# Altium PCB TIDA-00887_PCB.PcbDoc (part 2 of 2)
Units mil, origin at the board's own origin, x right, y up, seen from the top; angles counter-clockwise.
Board outline 2665 x 2727 mil, 4 copper layers (Top Layer, GND, 3p3V, Bottom Layer), stack 61.2 mil thick; 96 components, 53 nets, 301 pads, 167 vias.
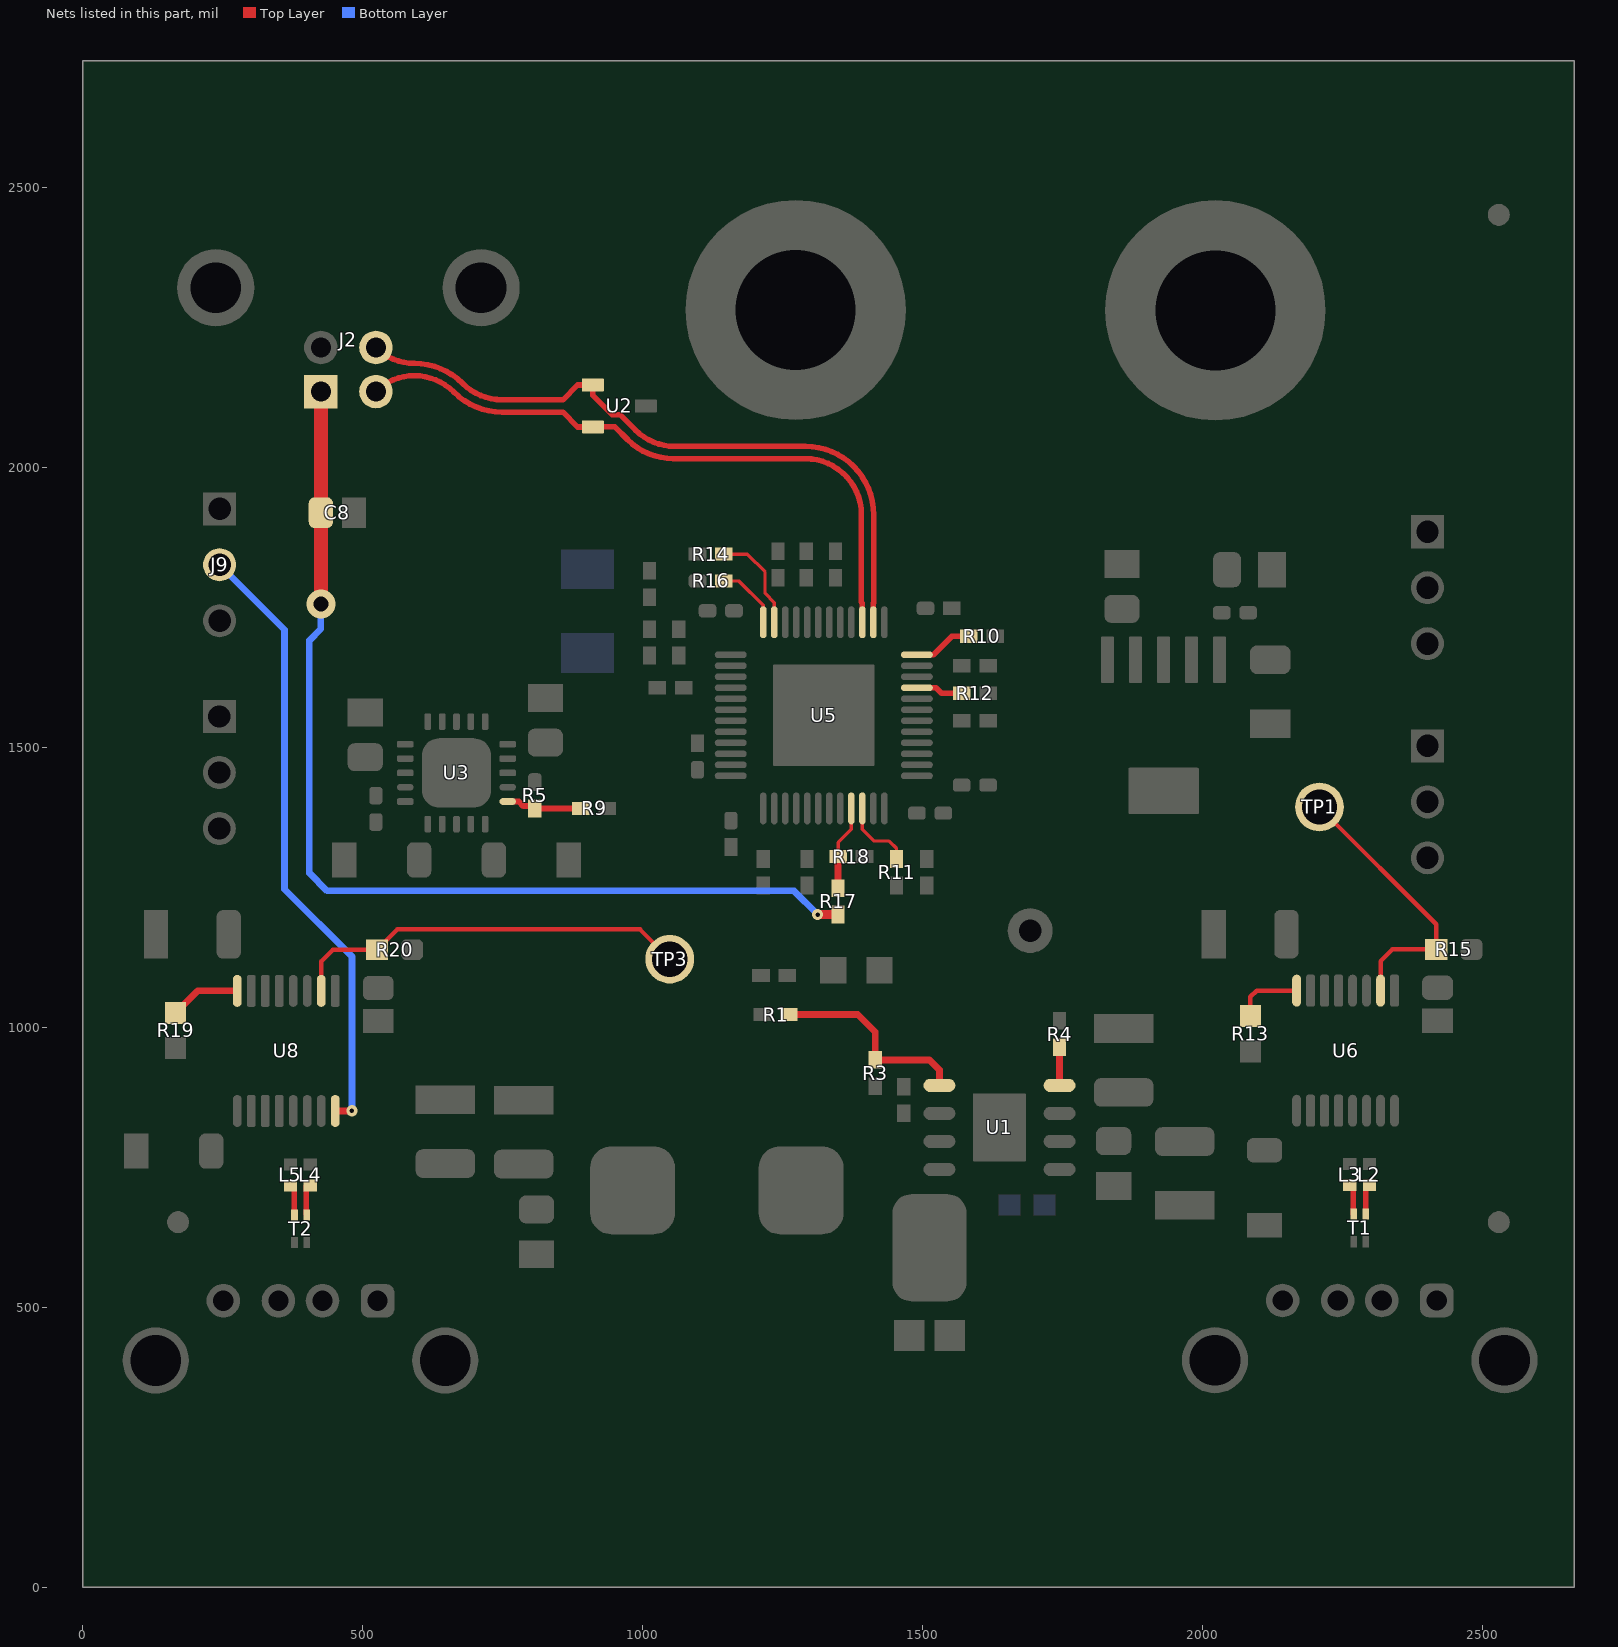
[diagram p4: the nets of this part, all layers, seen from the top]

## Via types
v1: diameter 19.68, hole 7.87, Top Layer to Bottom Layer, tented both sides, 115 vias
v2: diameter 19.68, hole 7.87, Top Layer to Bottom Layer, 30 vias
v3: diameter 34, hole 16, Top Layer to Bottom Layer, tented both sides, 13 vias
v4: diameter 19.68, hole 7.87, Top Layer to Bottom Layer, tented top, 6 vias
v5: diameter 80, hole 60, Top Layer to Bottom Layer, 2 vias
v6: diameter 51.77, hole 26.7, Top Layer to Bottom Layer, 1 vias

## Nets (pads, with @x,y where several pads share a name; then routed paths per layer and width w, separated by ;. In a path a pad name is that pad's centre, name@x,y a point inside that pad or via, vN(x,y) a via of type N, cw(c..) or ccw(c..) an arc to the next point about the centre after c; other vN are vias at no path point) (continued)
NetJ9_2: J9.2 U8.8 | length 1103.5
  Top Layer w12: U8.8@450.82,850.73 480.23,850.73 v1(480.58,851.08)
  Bottom Layer w12: J9.2@244.15,1826.73 360.28,1710.59 360.28,1246.89 480.58,1126.59 v1(480.58,851.08)
NetL2_2: L2.2 T1.3 | length 50.8
  Top Layer w10.01: T1.3@2292.19,666.21 L2.2@2292.19,717
NetL3_2: L3.2 T1.1 | length 50.8
  Top Layer w10.01: T1.1@2270.2,666.21 L3.2@2270.2,717
NetL4_2: L4.2 T2.3 | length 50.8
  Top Layer w10.01: T2.3@399.32,665.74 L4.2@399.32,716.53
NetL5_2: L5.2 T2.1 | length 50.8
  Top Layer w10.01: T2.1@377.33,665.74 L5.2@377.33,716.53
NetR1_2: R1.2 R3.1 U1.5 | length 367
  Top Layer w12: R1.2@1261.37,1022.95 1384.49,1022.95 1415.74,991.7 R3.1@1415.74,941.95 1512.64,941.95 1530.46,924.13 U1.5@1530.46,896.33
NetR4_1: R4.1 U1.4 | length 64.9
  Top Layer w12: U1.4@1745.03,896.33 R4.1@1745.03,961.22
NetR5_1: R5.1 R9.2 U3.16 | length 137
  Top Layer w10.5: U3.16@758.97,1403.66 778.69,1403.66 786.93,1395.41 803.24,1395.41 R5.1@807.43,1391.22 890.45,1391.22 R9.2@890.71,1391.49
NetR10_1: R10.1 U5.24 | length 106.3
  Top Layer w10: U5.24@1490.14,1666.01 1519.76,1666.01 1552.7,1698.94 R10.1@1582.76,1698.94
NetR11_1: R11.1 U5.10 | length 131.4
  Top Layer w6: U5.10@1392.7,1391.4 1392.7,1354.13 1413.77,1333.06 1440.46,1333.06 1453.8,1319.71 R11.1@1453.8,1300.94
NetR12_2: R12.2 U5.21 | length 84.1
  Top Layer w10: U5.21@1490.14,1606.96 1524.31,1606.96 1534.15,1597.11 R12.2@1570.18,1597.11
NetR13_2: R13.2 U6.16 | length 121.6
  Top Layer w8: R13.2@2086.1,1020.19 2086.1,1054.57 2097.3,1065.77 U6.16@2168.7,1065.77
NetR14_2: R14.2 U5.35 | length 183.3
  Top Layer w6: R14.2@1145.36,1845.74 1186.97,1845.74 1218.79,1813.92 1218.79,1775.41 1235.22,1758.98 U5.35@1235.22,1724.08
NetR15_1: R15.1 TP1.1 U6.10 | length 493.2
  Top Layer w8: TP1.1@2215.09,1387.56 2418.23,1184.42 R15.1@2418.23,1139.29 2339.56,1139.29 2318.7,1118.43 U6.10@2318.7,1065.77
NetR16_2: R16.2 U5.36 | length 118.4
  Top Layer w6: R16.2@1145.36,1797.74 1172.16,1797.74 1215.54,1754.37 U5.36@1215.54,1724.08
NetR17_2: R17.2 R18.2 U5.9 | length 152.2
  Top Layer w6: R18.2@1349.39,1305.32 1349.39,1330.47 1373.02,1354.09 U5.9@1373.02,1391.4
  Top Layer w12: R17.2@1349.39,1248.94 R18.2@1349.39,1305.32
NetR19_2: R19.2 U8.16 | length 126.4
  Top Layer w12: R19.2@165.66,1026.02 204.93,1065.3 U8.16@275.82,1065.3
NetR20_1: R20.1 TP3.1 U8.10 | length 721
  Top Layer w8: U8.10@425.82,1065.3 425.82,1117.96 446.69,1138.82 R20.1@525.35,1138.82 561.53,1175 995.53,1175 TP3.1@1048.53,1122
UP1_N: J2.2 U2.2 U5.27 | length 1170.3
  Top Layer w10.01: J2.2@523.53,2136.26 cw(c592.04,2067.76) 592.04,2164.63 cw(c592.04,2064.63) 662.75,2135.35 ccw(c749.01,2221.6) 749.01,2099.6 ; 749.01,2099.43 796.91,2099.43 857.53,2099.42 884.03,2072.93 U2.2@911.29,2072.93 ; U2.2@911.29,2073.13 950.41,2073.13 973.48,2050.05 ccw(c1054.94,2131.51) 1054.94,2016.31 1183.53,2016.31 1290.96,2016.31 cw(c1290.96,1916.31) 1390.96,1916.31 1390.96,1760.2 ; 1391.54,1758.79 1392.7,1757.63 U5.27@1392.7,1724.08
UP1_P: J2.3 U2.1 U5.26 | length 1237.8
  Top Layer w10.01: J2.3@523.53,2215 ccw(c592.04,2283.5) 592.04,2186.62 cw(c592.04,2064.63) 678.3,2150.89 ccw(c749.02,2221.6) 749.02,2121.6 ; 749.01,2121.43 796.91,2121.43 857.53,2121.43 884.03,2147.93 U2.1@911.29,2147.93 911.29,2129.38 945.53,2095.14 959.52,2095.14 987.05,2067.61 ccw(c1057.76,2138.32) 1057.76,2038.32 1290.96,2038.32 cw(c1290.96,1916.31) 1412.97,1916.31 1412.97,1759.03 ; U5.26@1412.39,1724.08 1412.39,1757.63
UP1_VBUS: C8.1 J2.1 R17.1 | length 1843.4
  Top Layer w16: v1(1312.95,1201.4) 1348.95,1201.4 R17.1@1349.61,1200.75
  Top Layer w24.75: v6(425.11,1756.43) C8.1@425.11,1919.79 425.11,2010.26 425.11,2073.26 J2.1@425.11,2136.26
  Bottom Layer w12: v6(425.11,1756.43) 425.11,1712.32 404.53,1691.75 404.53,1276 436.41,1244.13 1270.75,1244.13 1311.83,1203.04 v1@1311.97,1203.04
pads on no net: FID1.1 FID2.1 FID3.1 U3.9 U3.17 U5.2 U5.3 U5.4 U5.5 U5.6 U5.8 U5.16 U5.17 U5.19 U5.20 U5.22 U5.28 U5.29 U5.31 U5.32 U5.43 U5.44 U5.46 U5.47 U6.1 U8.1

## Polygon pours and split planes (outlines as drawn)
NetC2_2 on Top Layer "Top Layer-12p0" (solid, pour order 394): 1889.36,905.67 1946.43,962.75 1959.89,962.75 2014.89,962.75 2030.26,947.38 2030.26,798.49 2002.77,771 1993.53,771 1963.53,801 1888.53,801
NetC2_2 on Top Layer "Top Layer-12p0" (solid, pour order 392): 1783.41,909.55 1783.41,807 1899.53,807 1905.53,813 1905.53,909.55
NetC36_1 on Top Layer "Top Layer-VBUS" (solid, pour order 390): 2080.53,806 2170.96,806 2187.25,822.29 2187.25,824.6 2186.67,825.46 2188.68,827.47 2188.68,874.76 2223.68,874.76 2223.4,768.12 2209.28,754 2193.71,754 2116.38,754 2080.53,754
+3P3 on Top Layer "Top_Power" (solid, pour order 386): 2428.66,1075.61 2428.66,1049.24 2451.56,1049.24 2481.39,1049.24 2514.99,1082.85 2514.99,1135.64 2493.4,1157.24 2490.66,1157.24 2477.77,1157.24 2465.41,1150.69 2465.41,1112.36
+5V on Top Layer "Top Layer-VBUS_Sys_U6" (solid, pour order 388): 2226.3,1042.04 2226.35,1042.08 2226.35,1092.42 2226.42,1092.49 2226.42,1099.44 2234.73,1107.75 2234.73,1202.12 2228.25,1208.6 2161.44,1208.6 2138.97,1186.13 2138.97,1128.39 2142.86,1124.5 2162.88,1124.5 2186.06,1101.32 2186.06,1086.2 2186.06,1041.9 2226.22,1041.9
+3P3 on Top Layer "Top Layer-3p3_u6" (solid, remove dead copper, pour order 387): 2424.83,1092.09 2424.26,1092.66 2343.73,1092.66 2344.58,1091.81 2344.58,1037.84 2344.72,1037.98 2369.29,1037.98 2381.37,1050.05 2424.83,1050.05
+1P1 on Top Layer "Top Layer-1p0" (solid, pour order 384): 715.93,1533.18 716.11,1533 728.78,1533 743.6,1518.18 743.6,1510.86 743.6,1505.33 743.78,1505.15 769.31,1505.15 769.49,1505.33 769.49,1527.11 737.71,1558.88 723.96,1558.88 723.61,1559.24 717,1559.24
+5V on Top Layer "Top Layer-5p0" (solid, pour order 357): 616.67,1532.82 616.49,1532.64 603.82,1532.64 589,1517.82 589,1510.5 589,1504.97 588.82,1504.79 563.29,1504.79 563.11,1504.97 563.11,1526.75 594.89,1558.53 608.64,1558.53 608.99,1558.88 615.6,1558.88
NetC19_2 on Top Layer "Top Layer-c9-2" (solid, pour order 383): 715.53,1373.35 715.68,1286.38 719.81,1282.25 754.87,1282.25 754.38,1282.74 754.38,1322.01 741.13,1335.26 741.13,1336.77 741.56,1337.2 741.56,1358.2 726.14,1373.62 723.06,1373.62
NetC13_2 on Top Layer "Top Layer-c7-2" (solid, pour order 382): 621.15,1301.89 621.64,1302.38 621.64,1374.28 617.18,1378.73 608.24,1378.73 523.42,1378.73 514.36,1369.68 514.36,1356.75 514.36,1352.2 591.29,1275.28 621.31,1275.28
NetC38_1 on Top Layer "Top Layer-VBUS" (solid, pour order 381): 217.93,807.97 218.22,807.68 280.24,807.68 294.38,821.82 294.38,824.12 294.38,824.41 293.8,824.99 295.8,827 295.8,874.29 330.8,874.29 330.53,874.01 330.53,767.64 311.31,748.43 305.94,748.43 305.29,749.08 236.24,749.08 217.68,767.64 217.68,807.7
+5V on Top Layer "Top Layer-5p0" (solid, pour order 380): 599.72,779.35 1031,779.17 1036.64,773.53 1036.64,640.58 1025.5,651.73 793.16,651.73 760.74,619.3 726,619.31 647.37,619.13 635.72,630.77 635.72,699.27 599.9,735.1 599.9,738.19
NetC1_1 on Top Layer "Top Layer-c36-1" (solid, pour order 379): 1321.72,783.38 1385.75,783.38 1413.31,755.83 1515.74,755.83 1516.14,755.43 1550.16,755.43 1557.84,747.75 1557.84,744.82 1557.84,709.53 1557.84,654.33 1535.66,632.15 1456.51,632.15 1323.31,631.86 1315.81,639.36 1315.81,783.38 1334.51,783.38 1359.97,783.13
NetC2_2 on Top Layer "Top Layer-c37_2" (solid, pour order 378): 1721.82,795.8 1721.83,795.81 1721.83,851.21 1728.03,857.41 1730.71,857.41 1730.9,857.22 2021.11,857.22 2013.62,849.73 2013.62,767.64 2013.46,767.47 1921.74,767.47 1908.24,767.47 1902.05,773.66 1891.74,773.66 1890.8,774.6 1831.94,774.6 1814.13,792.41 1814.13,794.84
+5V on Top Layer "Top Layer-VBUS_Sys_U6" (solid, pour order 377): 333.43,1041.56 333.47,1041.61 333.47,1091.95 333.54,1092.02 333.54,1098.97 341.86,1107.28 341.86,1201.64 335.38,1208.12 268.56,1208.12 246.1,1185.66 246.1,1127.92 249.99,1124.03 270,1124.03 293.19,1100.84 293.19,1085.72 293.19,1041.43 333.34,1041.43
+1P1 on Top Layer "Top_Power" (solid, pour order 367): 1436.8,1368.94 1505.8,1368.94 1505.8,1392.66 1487.52,1410.94 1440.8,1410.94 1436.8,1414.94 1435.8,1414.94 1436.8,1413.94
+3P3 on Top Layer "Top_Power" (solid, pour order 363): 1181.33,1444.74 1177.33,1440.74 1177.33,1353.62 1137.33,1353.62 1137.33,1440.74 1134.33,1443.74 1134.33,1444.74
+3P3 on Top Layer "Top_Power" (solid, pour order 364): 1133.6,1670.74 1137.6,1674.74 1137.6,1755.95 1177.6,1755.95 1177.6,1674.74 1180.6,1671.74 1180.6,1670.74
+3P3 on Top Layer "Top_Power" (solid, pour order 365): 1441.05,1773.38 1500.69,1773.38 1513.7,1760.38 1513.7,1738.16 1479.48,1703.94 1440.8,1703.94 1437.8,1700.94 1426.42,1700.94 1426.42,1758.76
GND on Top Layer "Top_GND" (solid, remove dead copper, pour order 395): 30,2727 2640.2,2727 2640.2,0 30,0
+3P3 on Top Layer "Top_Power" (solid, pour order 369): 535.79,1075.14 535.79,1048.77 558.68,1048.77 588.51,1048.77 622.12,1082.38 622.12,1135.17 600.52,1156.77 597.79,1156.77 584.9,1156.77 572.53,1150.22 572.54,1111.88
+3P3 on Top Layer "Top_Power" (solid, pour order 375): 1892.53,1616 1892.53,1761 1879.53,1774 1744.53,1774 1744.53,1667.39 1795.92,1616
NetC12_2 on Top Layer "Top_Power" (solid, pour order 376): 2158.53,1631 2076.53,1631 2061.53,1616 2050.53,1616 2013.53,1616 2013.53,1750 2109.53,1750 2158.53,1701 2158.53,1631
+5V on Top Layer "Top_Power" (solid, remove dead copper, pour order 373): 424.23,1387.87 588.76,1387.87 588.76,1453.31 595.67,1453.36 595.67,1508.1 424.23,1508.1
NetC13_2 on Top Layer "Top Layer-C7_2" (solid, pour order 360): 295.57,1391.26 211.11,1391.24 189.29,1369.42 256.76,1301.95 257.66,1301.95 258.02,1301.59 299.31,1301.59 299.16,1387.67
+5V on Top Layer "Top_Power1" (solid, pour order 372): 1955.19,1708.38 1955.19,1850 2050.53,1850 2050.53,1729 2027,1729 1991.08,1693.08 1974.73,1693.08
+3P3 on Top Layer "Top Layer-3p3_u6" (solid, remove dead copper, pour order 358): 531.95,1091.62 531.39,1092.19 450.85,1092.19 451.71,1091.33 451.71,1037.36 451.85,1037.5 476.42,1037.5 488.49,1049.58 531.95,1049.58
+1P1 on Top Layer "Top_1p1_Power" (solid, remove dead copper, pour order 374): 744.43,1448.91 774.43,1448.91 774.43,1422.91 873.43,1422.91 873.43,1466.91 883.98,1477.46 992.27,1478.17 992.27,1532.91 794.43,1532.91 774.43,1512.91 770.43,1512.91 744.43,1512.91 743.43,1511.91 743.43,1448.91
GND on GND "L2_GND" (solid, remove dead copper, pour order 370): 30,2727 2640.2,2727 2640.2,0 30,0
+1P1 on Bottom Layer "Bott Layer-1p0" (solid, pour order 393): 1466.93,1454.53 1495.95,1454.53 1495.95,1521.68 1453.39,1564.24 1431.06,1564.24 1412.08,1545.26 1412.08,1544.28 1408.59,1540.79 1408.59,1452.57
NetC36_1 on Bottom Layer "Bottom Layer-VBUS" (solid, remove dead copper, pour order 389): 2448.91,661.97 2315.91,794.97 2291.91,818.97 2163.91,818.97 2154.91,809.97 2154.91,753.97 2160.91,747.97 2244.91,747.97 2384.41,608.47 2448.91,608.47
NetC36_1 on Bottom Layer "Bot_5V" (solid, remove dead copper, pour order 391): 2431.64,679.31 2378.47,679.31 2378.47,493.94 2400.41,472 2444.41,472 2466.41,494 2466.41,644.54
NetC38_1 on Bottom Layer "Bottom Layer-VBUS" (solid, remove dead copper, pour order 366): 556.03,661.5 423.03,794.5 399.03,818.5 271.03,818.5 262.03,809.5 262.03,753.5 268.03,747.5 352.03,747.5 491.53,608 556.03,608
NetC38_1 on Bottom Layer "Bot_5V" (solid, remove dead copper, pour order 368): 538.77,678.83 485.59,678.83 485.59,493.47 507.54,471.53 551.53,471.53 573.54,493.53 573.53,644.07
GND on Bottom Layer "Bot_GND" (solid, remove dead copper, pour order 396): 30,2727 2640.2,2727 2640.2,0 30,0
+1P1 on Bottom Layer "Bott_1p1" (solid, remove dead copper, pour order 361): 1179.05,1334.5 1365.11,1334.5 1447.67,1335 1495.91,1383.23 1495.91,1459.79 1434.1,1459.79 1163.95,1459.79 1122.01,1417.85 1122.01,1391.55
+1P1 on Bottom Layer "Bott_1p1a" (solid, remove dead copper, pour order 362): 1227.91,1723.55 1350.67,1723.55 1350.67,1648.68 1350.67,1635.67 1243.21,1635.67 1243.21,1518.57 1165.08,1387.98 1125.63,1387.98 1009,1504.61
+1P1 on Bottom Layer "Bottom Layer-1p1" (solid, remove dead copper, pour order 359): 883.87,1538.16 1098.12,1537.98 1098.12,1472.31 884.64,1472.31 873.43,1483.52 873.43,1527.73
+5V on 3p3V "3P3_+5VB" (solid, remove dead copper, pour order 354): 1881,1526 1620,1265 1620,970 1716.24,873.75 1716.24,755.83 1906.63,946.21 1906.63,1530
+5V on 3p3V "3P3_+5Va" (solid, remove dead copper, pour order 355): 2016.28,827.28 2250.96,1061.96 2250.96,1117 2250.65,1198 2019.89,1428.76 2019.89,1832.84 1998.73,1854 1958,1854 1877,1773 1877,879.51
+5V on 3p3V "3P3_+5V" (solid, remove dead copper, pour order 356): 270,1200 420,1350 420,1380 420,1470 435,1485 465,1485 548.21,1401.79 548.21,831.79 660,720 765,720 1005,480 1095,480 1410,480 1950,1020 2077.35,1020 2132,965.35 2132,-62 2055,15 270,15
+3P3 on 3p3V "3p3V" (solid, remove dead copper, pour order 371): 30,2727 2640.2,2727 2640.2,0 30,0

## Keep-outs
Keep-Out Layer:
  lines w10: -5,-5 2670,-5 2670,2732 -5,2732 -5,-5
  text ".Layer_Name" at -4149.47,-1063.99 h60

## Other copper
Top Layer:
  pour cut-out: 888.08,467.91 1376.52,468.23 1376.52,630.77 888.08,630.77
  pour cut-out: 901.34,957.51 1376.52,957.2 1376.52,792.41 901.34,792.41
  pour cut-out: 854,1854.21 854.21,1854 948.87,1854 948.87,1633.52 853.81,1633.52
  pour cut-out: 2255.63,653.5 2307.03,653.5 2308.1,652.43 2308.1,625.13 2255.56,625.13 2255.63,625.21
  pour cut-out: 363.14,652.37 414.53,652.37 415.6,651.3 415.6,624 363.06,624 363.14,624.08
  pour cut-out: 1896.04,1803.68 1896.04,1775.18 1895.25,1774.4 1816.35,1774.4 1817.01,1775.06 1817.01,1803.6
  pour cut-out: 1451.03,1439.1 1453.95,1436.18 1554.76,1436.18 1554.76,1394.5 1525.12,1394.5 1495.23,1424.4 1451.03,1424.4
  pour cut-out: 920.6,950.1 1323.4,950.1 1323.4,467.93 920.6,467.93
  text ".Layer_Name" at -4149.47,-1063.99 h60
GND:
  pour cut-out: 854,1854.21 854.21,1854 948.87,1854 948.87,1633.52 853.81,1633.52
  pour cut-out: 888.08,957.51 1377.16,957.51 1377.16,467.93 888.08,467.93
3p3V:
  pour cut-out: 854,1854.21 854.21,1854 948.87,1854 948.87,1633.52 853.81,1633.52
  pour cut-out: 1225.89,1655.57 1421.39,1655.57 1421.39,1459.8 1225.89,1459.8
  pour cut-out: 888.08,957.51 1377.16,957.51 1377.16,467.93 888.08,467.93
Bottom Layer:
  pour cut-out: 854,1854.21 854.21,1854 948.87,1854 948.87,1633.52 853.81,1633.52
  pour cut-out: 888.08,957.51 1377.16,957.51 1377.16,467.93 888.08,467.93
  text ".Layer_Name" at -4149.47,-1063.99 h60

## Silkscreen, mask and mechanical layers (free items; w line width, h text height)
Top Overlay:
  rectangle: 2245.79,660.33 2255.38,669.4
  region: 2108.53,873 2108.53,841.15 2140.98,841.15 2140.98,873
  region: 2311.12,781.82 2301.53,781.82 2301.53,772.75 2311.12,772.75
  rectangle: 2251.25,770.8 2260.84,779.87
  region: 214.53,874.29 214.53,840.67 248.11,840.67 248.11,874.29
  lines w5: 496.19,983.53 559.18,983.53 ; 496.19,1098.53 559.18,1098.53 ; 2389.06,984 2452.05,984 ; 2389.06,1099 2452.05,1099
  lines w10: 476.53,884.11 537.53,692 ; 1748.23,1762.68 1793.54,1620
  text "GND" at 1158.6,2549 h90
  text "+12V" at 1844,2546 h90
  text "0" at 316.13,1887.06 h75
  text "0" at 2265.53,1835 h75
  text "1" at 343.13,1705.06 h75
  text "U6-DEN" at 162.53,1667 h60 r90
  text "1" at 2304.13,1653.06 h75
  text "U4-DEN" at 2556.53,1646 h60 r90
  text "0" at 316.29,1504 h78
  text "0" at 2266.53,1453 h75
  text "1" at 343.29,1322 h75
  text "1" at 2304.29,1270 h75
  text "U6-VEN" at 162.53,1261 h60 r90
  text "U4-VEN" at 2556.53,1210 h60 r90
  text "TIDA-00887" at 106,145 h125
  text ".Layer_Name" at -4149.47,-1063.99 h60
Bottom Overlay:
  lines w6: 849.36,1714.14 849.36,1774.14 ; 961.36,1711.74 961.36,1771.74
  text ".Layer_Name" at -4149.47,-1063.99 h30
Top Paste:
  text ".Layer_Name" at -4149.47,-1063.99 h60
Bottom Paste:
  text ".Layer_Name" at -4149.47,-1063.99 h60
Top Solder:
  text ".Layer_Name" at -4149.47,-1063.99 h60
  text ".Layer_Name" at -4149.47,-1063.99 h60
Bottom Solder:
  text ".Layer_Name" at -4149.47,-1063.99 h60
Drill Guide:
  text ".Layer_Name" at -4149.47,-1063.99 h60
M1 Board Outline:
  the board outline again, w10
  text ".Layer_Name" at -4149.47,-1063.99 h60
M2 Board Dimensions:
  rectangle: -4601.47,-605.5 -4226.47,-480.5
  rectangle: -4726.47,-480.5 -4601.47,-355.5
  lines w7: -4726.47,-480.5 -3726.47,-480.5 ; -4601.47,-605.5 -4601.47,-355.5 ; -4476.47,-605.5 -4476.47,-355.5 ; -4226.47,-605.5 -4226.47,-355.5 ; -3976.47,-605.5 -3976.47,-355.5 ; -4726.47,-605.5 -4726.47,-355.5 -3726.47,-355.5 -3726.47,-605.5 -4726.47,-605.5
  text ".Layer_Name" at -4149.47,-1063.99 h60
M3 3D STEP Top:
  text ".Layer_Name" at -4149.47,-1063.99 h60
M4 3D STEP Bottom:
  text ".Layer_Name" at -4149.47,-1063.99 h60
M5 Assembly Top:
  lines w10: -5018.47,-1135.67 1581.53,-1135.67 ; -5018.47,-932.33 1583.53,-932.33 ; -5018.47,-729 -5018.47,-1339 -1013.47,-1339 1583.53,-1339 1583.53,-729 -5017.97,-729 -5017.97,-1339 -3442.47,-1339 ; -2553.47,-1339 -2553.47,-729 ; -1286.47,-932.33 -1286.47,-729 ; -446.47,-932.33 -446.47,-729 ; 175.53,-1345.5 175.53,-1142.67
  text "Y1" at 874.53,1722.82 h40
  text "COMPONENTS MARKED 'DNP' SHOULD NOT BE POPULATED." at -3572.97,-524 h60
  text "ASSEMBLY VARIANT:" at -3573.47,-639.5 h60
  text ".VariantName" at -2537.47,-639.5 h60
  text "PCB VIEWED FROM TOP SIDE" at -4954.97,-861.17 h60
  text "BOARD #:" at -2478.47,-861.17 h60
  text ".PRJ_Number" at -1932.97,-861.17 h60
  text "REV:" at -1088.47,-861.17 h60
  text ".PCB_Rev" at -796.97,-861.17 h60
  text "SVN REV:" at -250.47,-861.17 h60
  text ".VersionControl_RevNumber" at 255.53,-861.17 h60
  text "TID #:" at -2478.47,-1064.5 h60
  text ".TID" at -1932.97,-1064.5 h60
  text "PLOT NAME =" at -4954.97,-1269.84 h60
  text ".plot_File_Name" at -4149.47,-1269.84 h60
  text "GENERATED    :" at -2476.47,-1269.84 h60
  text ".Print_Date" at -1606.97,-1269.84 h60
  text ".Print_Time" at -877.97,-1269.84 h60
  text "TEXAS INSTRUMENTS" at 386.53,-1269.84 h60
M6 Assembly Bottom:
  lines w10: -5018.97,-932.83 1583.03,-932.83 ; -5016.97,-1136.17 1583.03,-1136.17 ; -3610.97,-1346 -3610.97,-1143.17 ; -2988.97,-932.83 -2988.97,-729.5 ; -2148.97,-932.83 -2148.97,-729.5 ; -881.97,-1339.5 -881.97,-729.5 ; 7.03,-1339.5 1582.53,-1339.5 1582.53,-729.5 -5018.97,-729.5 -5018.97,-1339.5 -2421.97,-1339.5 1583.03,-1339.5 1583.03,-729.5
  text "COMPONENTS MARKED 'DNP' SHOULD NOT BE POPULATED." at 1375.53,-523.5 h60
  text ".VariantName" at 331.53,-639.5 h60
  text "ASSEMBLY VARIANT:" at 1370.53,-639.5 h60
  text ".VersionControl_RevNumber" at -3690.97,-861.67 h60
  text "SVN REV:" at -3184.97,-861.67 h60
  text ".PCB_Rev" at -2638.47,-861.67 h60
  text "REV:" at -2346.97,-861.67 h60
  text ".PRJ_Number" at -1502.47,-861.67 h60
  text "BOARD #:" at -956.97,-861.67 h60
  text "PCB VIEWED FROM BOTTOM SIDE" at 1519.53,-861.67 h60
  text ".TID" at -1502.47,-1065 h60
  text "TID #:" at -956.97,-1065 h60
  text "TEXAS INSTRUMENTS" at -3821.97,-1270.34 h60
  text ".Print_Time" at -2557.47,-1270.34 h60
  text ".Print_Date" at -1828.47,-1270.34 h60
  text "GENERATED    :" at -958.97,-1270.34 h60
  text ".plot_File_Name" at 714.03,-1270.34 h60
  text "PLOT NAME =" at 1519.53,-1270.34 h60
M9 Title Sheet:
  drawing of 53 lines, arcs and shapes, not listed
  text "5" at 6004.03,7831 h70
  text "6" at 8509.03,7831 h70
  text "A" at -5142.97,6688 h70
  text "A" at 9657.03,6688 h70
  text "B" at -5142.97,4308 h70
  text "B" at 9657.03,4308 h70
  text "C" at -5142.97,1933 h70
  text "C" at 9657.03,1933 h70
  text "PROJECT TITLE:" at 6617.03,72 h45
  text ".PRJ_Title" at 6667.03,-61.33 h70
  text "DESIGNED FOR:" at 6617.03,-229 h45
  text ".PRJ_Customer" at 6667.03,-369 h70
  text "D" at -5142.97,-437 h70
  text "D" at 9657.03,-437 h70
  text "FILE NAME:" at 6617.03,-529 h45
  text ".PCB_File_Name_No_Path" at 6667.03,-649 h70
  text "Texas Instruments (TI) and/or its licensors do not warrant the accuracy or completeness of this specification" at 1647.53,-810.84 h45
  text "ENGINEER:" at 6617.03,-819 h45
  text "LAYOUT BY:" at 8122.03,-819 h45
  text "or any information contained therein. TI and/or its licensors do not warrant that this design will meet" at 1602.55,-923.5 h45
  text ".PRJ_Engineer" at 6667.03,-973.99 h70
  text ".PCB_Layout" at 8172.53,-973.99 h70
  text "the specifications, will be suitable for your application or fit for any particular purpose, or will operate in" at 1602.55,-1036.17 h45
  text ".Layer_Name" at -4149.47,-1063.99 h60
  text "ALTIUM DESIGNER VERSION:" at 8122.03,-1129 h45
  text "an implementation. TI and/or its licensors do not warrant that the design is production worthy. You should" at 1602.55,-1148.83 h45
  text "completely validate and test your design implementation to confirm the system functionality for your application." at 1647.53,-1261.5 h45
  text ".print_Scale" at 6667.03,-1262.33 h70
  text ".Application_BuildNumber" at 8172.53,-1262.33 h70
  text "1" at -3986.63,-1469 h70
  text "2" at -1490.97,-1469 h70
  text "3" at 998.38,-1469 h70
  text "4" at 3505.05,-1469 h70
  text "5" at 6004.03,-1469 h70
  text "6" at 8509.03,-1469 h70
M10 Fab Notes:
  drawing of 190 lines, arcs and shapes, not listed
  text "DESIGN INFORMATION" at 7654.55,5822.5 h60
  text "MIN. TRACK WIDTH:" at 7009.99,5642.5 h60
  text "5" at 8106.24,5642.5 h60
  text "MIL" at 8260.99,5642.5 h60
  text "MIN. CLEARANCE:" at 7009.99,5510.5 h60
  text "0.2" at 8046.24,5510.5 h60
  text "mm" at 8260.99,5510.5 h60
  text "ADDITIONAL NOTES:" at 167.79,5493.48 h100
  text "MIN. VIA PAD SIZE:" at 7009.99,5378.5 h60
  text "9.7" at 8076.25,5378.5 h60
  text "MIL" at 8260.99,5378.5 h60
  text "1. ALL HIGH SPEED TRACES HAVE THE SOLDER MASK ELIMINATED" at 167.79,5243.48 h100
  text "0.05mm (2MIL)" at 7704.99,5236.79 h60
  text "MINIMUM ANNULAR RING" at 6680.76,5232.5 h60
  text "EXTERNAL" at 8412.99,5232.5 h60
  text "PER" at 6880.76,5114.5 h60
  text "IPC-D-275 CLASS 2 LEVEL C" at 7100.76,5114.5 h60
  text "2. DO NOT PLATE LAYER 1 WITH ADDITIONAL COPPER EXCEPT AS" at 167.79,5043.48 h100
  text "MIL, HOLES" at 8588.99,5002.21 h60
  text "+/-" at 8196.53,5001.5 h60
  text "+/-" at 9050.53,5001.5 h60
  text "REGISTRATION TOLERANCES:" at 6680.76,4996.5 h60
  text "METAL" at 7880.53,4996.5 h60
  text "2" at 8456.74,4996.5 h60
  text "2" at 9289.74,4996.5 h60
  text "MIL" at 9405.99,4996.5 h60
  text "+/-" at 9050.53,4883.5 h60
  text "HOLE SIZE TOLERANCE (UNLESS OTHERWISE SPECIFIED):" at 6680.76,4878.5 h60
  text "2" at 9289.74,4878.5 h60
  text "MIL" at 9405.99,4878.5 h60
  text "NEEDED FOR PLATED THRU HOLES" at 467.79,4843.48 h100
  text "MATERIAL:" at 6605.99,4669.04 h60
  text "IMPEDANCE CONTROL" at 142.53,4658 h100
  text "FR-4 High Tg" at 7592.44,4528.71 h60
  text "X" at 6878.53,4521 h60
  text "FR-408" at 7027,4520.14 h60
  text "OTHER" at 8514.99,4520.14 h60
  text "All differential Pairs are 90 ohms differential impedance. +/- 10%" at 142.53,4480 h100
  text "62 MIL (1.6mm) +/-10%" at 7347.1,4357.42 h60
  text "THICKNESS:" at 6680.76,4353.14 h60
  text "X" at 7218.93,4353.14 h60
  text "OTHER" at 8631.99,4353.14 h60
  text "TOLERANCE:" at 6680.76,4195.14 h60
  text "X" at 7520.07,4195.14 h60
  text "ANSI IPC-6012 TYPE 3 CLASS 2" at 7707.01,4195.14 h60
  text "OTHER +/-" at 7706.99,4039.14 h60
  text "BOW & TWIST:" at 6680.76,3882.14 h60
  text "X" at 7520.07,3882.14 h60
  text "ANSI IPC-6012 TYPE 3 CLASS 2" at 7707.01,3882.14 h60
  text "OTHER +/-" at 7706.99,3723.63 h60
  text "DRILLING:" at 6605.99,3585.14 h60
  text "REFERENCE:" at 6680.76,3468.14 h60
  text "X" at 7328.99,3468.14 h60
  text "AS SHOWN" at 7515.99,3468.14 h60
  text "X" at 8229.99,3468.14 h60
  text "NC_DRILL FILES" at 8366.99,3468.14 h60
  text "PTH MIN COPPER THICKNESS:" at 6680.76,3310.14 h60
  text "X" at 8030.99,3310.14 h60
  text "1MIL" at 8167.99,3310.14 h60
  text "OTHER" at 8664.99,3310.14 h60
  text "BOARD FINISH:" at 6605.99,3151.14 h60
  text "SILKSCREEN:" at 6761.22,3033.14 h60
  text "X" at 7709.99,3033.14 h60
  text "TOP" at 7835.99,3033.14 h60
  text "X" at 8219.99,3033.14 h60
  text "BOTTOM" at 8346.99,3033.14 h60
  text "SILKSCREEN COLOR:" at 6761.22,2866.14 h60
  text "X" at 7708.95,2866.14 h60
  text "WHITE" at 7835.99,2866.14 h60
  text "OTHER" at 8346.99,2866.14 h60
  text "RED" at 8923.58,2708.23 h60
  text "GREEN" at 7966.99,2706.94 h60
  text "OTHER" at 8584.99,2706.94 h60
  text "X" at 8433.47,2703.32 h60
  text "SOLDER RESIST COLOR:" at 6761.22,2696.14 h60
  text "X" at 8429.85,2544.18 h60
  text "MATTE" at 7966.99,2536.94 h60
  text "SEMI-GLOSS" at 8584.53,2536.3 h60
  text "IMMERSION GOLD (ENIG)" at 7666.99,2348.42 h60
  text "ENEPIG" at 9004.53,2345.14 h60
  text "SURFACE FINISH:" at 6605.99,2344.14 h60
  text "X" at 7480.05,2344.14 h60
  text "IMM. TIN/SILVER OR EQUIV" at 6935.53,2187.14 h60
  text "OTHER" at 8366.99,2187.14 h60
  text "ARRAY/PANEL:" at 6605.99,2008.14 h60
  text "CUT AND TRIM PER M1 BOARD OUTLINE" at 7667,2003.85 h60
  text "N.C. ROUTE" at 7666.99,1852.14 h60
  text "X" at 8345.99,1852.14 h60
  text "V. SCORE" at 8532.99,1852.14 h60
  text "CERTIFICATION:" at 6605.99,1715.14 h60
  text "MATERIALS AND WORKMANSHIP FOR ALL PCBS" at 7330.99,1715.14 h60
  text "TO MEET OR EXCEED THE REQUIREMENTS OF:" at 7330.99,1617.14 h60
  text "X" at 6957.5,1480.63 h60
  text "ANSI IPC-A-600F CLASS ->" at 7096.5,1480.63 h60
  text "X" at 8735.55,1480.63 h60
  text "2" at 8854.5,1480.64 h60
  text "1" at 8539.5,1479.14 h60
  text "3" at 9208.5,1479.14 h60
  text "X" at 6959.55,1321.14 h60
  text "UL 94V-0" at 7096.5,1321.14 h60
  text "X" at 7771.55,1321.14 h60
  text "RoHS" at 7908.5,1321.14 h60
  text "OTHER" at 8552.9,1321.14 h60
  text "PER ORDER" at 8949.96,1321.14 h60
  text "ADDITIONAL REQUIREMENTS:" at 6605.99,1180.14 h60
  text "MICROSECTION:" at 6680.76,1065.14 h60
  text "YES" at 7586.5,1065.14 h60
  text "REQUIRED" at 8447.99,908.99 h60
  text "BARE BOARD ELEC. TEST:" at 6680.76,906.14 h60
  text "NONE" at 7986.5,906.14 h60
  text "X" at 8320.99,906.14 h60
  text "PER ORDER" at 9039.99,906.14 h60
  text "MANUFACTURER'S UL:" at 6680.76,749.14 h60
  text "RAIL" at 7846.5,744.85 h60
  text "METAL" at 8338.31,744.85 h60
  text "X" at 8713.53,744.5 h60
  text "SILK" at 8849.99,744.85 h60
  text ".Layer_Name" at -4149.47,-1063.99 h60
M11 Gerber Information:
  lines w10: -5018.47,-1135.67 1581.53,-1135.67 ; -5018.47,-932.33 1583.53,-932.33 ; -5018.47,-729 -5018.47,-1339 -1013.47,-1339 1583.53,-1339 1583.53,-729 -5017.97,-729 -5017.97,-1339 -3442.47,-1339 ; -2553.47,-1339 -2553.47,-729 ; -1286.47,-932.33 -1286.47,-729 ; -446.47,-932.33 -446.47,-729 ; 175.53,-1345.5 175.53,-1142.67
  text "ALL ARTWORK VIEWED FROM TOP SIDE" at -4954.97,-861.17 h60
  text "BOARD #:" at -2478.47,-861.17 h60
  text ".PRJ_Number" at -1932.97,-861.17 h60
  text "REV:" at -1088.47,-861.17 h60
  text ".PCB_Rev" at -796.97,-861.17 h60
  text "SVN REV:" at -250.47,-861.17 h60
  text ".VersionControl_RevNumber" at 255.53,-861.17 h60
  text "LAYER NAME =" at -4954.97,-1063.99 h60
  text "TID #:" at -2478.47,-1064.5 h60
  text ".TID" at -1932.97,-1064.5 h60
  text "PLOT NAME =" at -4954.97,-1269.84 h60
  text ".plot_File_Name" at -4149.47,-1269.84 h60
  text "GENERATED    :" at -2476.47,-1269.84 h60
  text ".Print_Date" at -1606.97,-1269.84 h60
  text ".Print_Time" at -877.97,-1269.84 h60
  text "TEXAS INSTRUMENTS" at 386.53,-1269.84 h60
M12 Stackup:
  drawing of 528 lines, arcs and shapes, not listed
  text "Layer" at 254.68,7053.5 h60
  text "Name" at 664.6,7053.5 h60
  text "Material" at 1594.34,7053.5 h60
  text "Thickness" at 2454.11,7053.5 h60
  text "Constant" at 3103.94,7053.5 h60
  text "Board Layer Stack" at 3673.8,7053.5 h60
  text "Board Layer Stack" at 4793.49,7053.5 h60
  text "1" at 254.68,6933.5 h60
  text "Top Overlay" at 664.6,6933.5 h60
  text "2" at 254.68,6813.5 h60
  text "Top Solder" at 664.6,6813.5 h60
  text "Solder Resist" at 1594.34,6813.5 h60
  text "0.40mil" at 2454.11,6813.5 h60
  text "3.5" at 3103.94,6813.5 h60
  text "3" at 254.68,6693.5 h60
  text "Top Layer" at 664.6,6693.5 h60
  text "Copper" at 1594.34,6693.5 h60
  text "1.42mil" at 2454.11,6693.5 h60
  text "4" at 254.68,6573.5 h60
  text "Dielectric1" at 664.6,6573.5 h60
  text "FR408HR" at 1594.34,6573.5 h60
  text "5.50mil" at 2454.11,6573.5 h60
  text "3.6" at 3103.94,6573.5 h60
  text "5" at 254.68,6453.5 h60
  text "GND" at 664.6,6453.5 h60
  text "Copper" at 1594.34,6453.5 h60
  text "1.42mil" at 2454.11,6453.5 h60
  text "6" at 254.68,6333.5 h60
  text "Dielectric 2" at 664.6,6333.5 h60
  text "FR4" at 1594.34,6333.5 h60
  text "44.53mil" at 2454.11,6333.5 h60
  text "4.2" at 3103.94,6333.5 h60
  text "7" at 254.68,6213.5 h60
  text "3p3V" at 664.6,6213.5 h60
  text "Copper" at 1594.34,6213.5 h60
  text "1.42mil" at 2454.11,6213.5 h60
  text "8" at 254.68,6093.5 h60
  text "Dielectric 3" at 664.6,6093.5 h60
  text "FR408HR" at 1594.34,6093.5 h60
  text "5.50mil" at 2454.11,6093.5 h60
  text "3.6" at 3103.94,6093.5 h60
  text "9" at 254.68,5973.5 h60
  text "Bottom Layer" at 664.6,5973.5 h60
  text "Copper" at 1594.34,5973.5 h60
  text "1.42mil" at 2454.11,5973.5 h60
  text "10" at 254.68,5853.5 h60
  text "Bottom Solder" at 664.6,5853.5 h60
  text "Solder Resist" at 1594.34,5853.5 h60
  text "0.40mil" at 2454.11,5853.5 h60
  text "3.5" at 3103.94,5853.5 h60
  text "11" at 254.68,5733.5 h60
  text "Bottom Overlay" at 664.6,5733.5 h60
  text "ADDITIONAL NOTES:" at 167.79,5493.48 h100
  text "1. ALL HIGH SPEED TRACES HAVE THE SOLDER MASK ELIMINATED" at 167.79,5243.48 h100
  text "2. DO NOT PLATE LAYER 1 WITH ADDITIONAL COPPER EXCEPT AS" at 167.79,5043.48 h100
  text "NEEDED FOR PLATED THRU HOLES" at 467.79,4843.48 h100
  text "IMPEDANCE CONTROL" at 142.53,4658 h100
  text "All differential Pairs are 90 ohms differential impedance. +/- 10%" at 142.53,4480 h100
  text ".Layer_Name" at -4149.47,-1063.99 h60
M13 Component Bodies Top:
  text ".Layer_Name" at -4149.47,-1063.99 h60
M14 Component Bodies Bottom:
  text ".Layer_Name" at -4149.47,-1063.99 h60
M15 Courtyards Top:
  text ".Layer_Name" at -4149.47,-1063.99 h60
M16 Courtyards Bottom:
  text ".Layer_Name" at -4149.47,-1063.99 h60
Drill Drawing:
  lines w10: -3004.37,6253.1 -3004.37,6266.91 -2990.56,6280.72 -3004.37,6294.54 -3004.37,6308.35 -2990.56,6308.35 -2976.75,6294.54 -2962.93,6308.35 -2949.12,6308.35 -2949.12,6294.54 -2962.93,6280.72 -2949.12,6266.91 -2949.12,6253.1 -2962.93,6253.1 -2976.75,6266.91 -2990.56,6253.1 -3004.37,6253.1 ; -3004.37,6377.42 -2976.75,6391.23 -2949.12,6377.42 -2962.93,6405.04 -2949.12,6432.67 -2976.75,6418.86 -3004.37,6432.67 -2990.56,6405.04 -3004.37,6377.42 ; -3004.37,6556.99 -2949.12,6556.99 -2976.75,6501.74 -3004.37,6556.99 ; -3004.37,6764.19 -2990.56,6764.19 -2990.56,6750.38 -2962.93,6750.38 -2962.93,6764.19 -2949.12,6764.19 -2949.12,6791.82 -2962.93,6791.82 -2962.93,6805.63 -2990.56,6805.63 -2990.56,6791.82 -3004.37,6791.82 -3004.37,6764.19 ; -2993.32,6264.15 -2993.32,6272.43 -2985.04,6280.72 -2993.32,6289.01 -2993.32,6297.3 -2985.04,6297.3 -2976.75,6289.01 -2968.46,6297.3 -2960.17,6297.3 -2960.17,6289.01 -2968.46,6280.72 -2960.17,6272.43 -2960.17,6264.15 -2968.46,6264.15 -2976.75,6272.43 -2985.04,6264.15 -2993.32,6264.15 ; -2993.32,6388.47 -2976.75,6396.75 -2960.17,6388.47 -2968.46,6405.04 -2960.17,6421.62 -2976.75,6413.33 -2993.32,6421.62 -2985.04,6405.04 -2993.32,6388.47 ; -2993.32,6769.71 -2985.04,6769.71 -2985.04,6761.43 -2968.46,6761.43 -2968.46,6769.71 -2960.17,6769.71 -2960.17,6786.29 -2968.46,6786.29 -2968.46,6794.58 -2985.04,6794.58 -2985.04,6786.29 -2993.32,6786.29 -2993.32,6769.71
  lines w12: -3054.47,6091.48 -1076.44,6091.48 ; -3054.47,7334.68 -1076.44,7334.68 ; -2716.6,5967.16 -2716.6,7459 ; -2384.6,5967.16 -2384.6,7459 ; -1748.04,5967.16 -1748.04,7459 ; -1488.9,5967.16 -1488.9,7459 ; -3054.47,5967.16 -1076.44,5967.16 -1076.44,7459 -3054.47,7459 -3054.47,5967.16
  text "Symbol" at -2979.87,7371.98 h72
  text "Quantity" at -2679.31,7371.98 h72
  text "Finished Hole Size" at -2347.31,7371.98 h72
  text "Plated" at -1710.74,7371.98 h72
  text "Hole Type" at -1451.6,7371.98 h72
  text "151" at -2679.31,7247.66 h60
  text "7.87mil (0.200mm)" at -2347.31,7247.66 h60
  text "PTH" at -1710.74,7247.66 h60
  text "Round" at -1451.6,7247.66 h60
  text "G" at -3005.16,7237.67 h55.25
  text "13" at -2679.31,7123.34 h60
  text "16.00mil (0.406mm)" at -2347.31,7123.34 h60
  text "PTH" at -1710.74,7123.34 h60
  text "Round" at -1451.6,7123.34 h60
  text "I" at -2995.95,7113.34 h55.25
  text "1" at -2679.31,6999.02 h60
  text "26.70mil (0.678mm)" at -2347.31,6999.02 h60
  text "PTH" at -1710.74,6999.02 h60
  text "Round" at -1451.6,6999.02 h60
  text "H" at -3005.16,6989.02 h55.25
  text "4" at -2679.31,6874.7 h60
  text "36.00mil (0.914mm)" at -2347.31,6874.7 h60
  text "PTH" at -1710.74,6874.7 h60
  text "Round" at -1451.6,6874.7 h60
  text "B" at -3005.16,6864.7 h55.25
  text "8" at -2679.31,6750.38 h60
  text "36.22mil (0.920mm)" at -2347.31,6750.38 h60
  text "PTH" at -1710.74,6750.38 h60
  text "Round" at -1451.6,6750.38 h60
  text "13" at -2679.31,6626.06 h60
  text "40.00mil (1.016mm)" at -2347.31,6626.06 h60
  text "PTH" at -1710.74,6626.06 h60
  text "Round" at -1451.6,6626.06 h60
  text "A" at -3005.16,6616.07 h55.25
  text "2" at -2679.31,6501.74 h60
  text "60.00mil (1.524mm)" at -2347.31,6501.74 h60
  text "PTH" at -1710.74,6501.74 h60
  text "Round" at -1451.6,6501.74 h60
  text "2" at -2679.31,6377.42 h60
  text "63.00mil (1.600mm)" at -2347.31,6377.42 h60
  text "PTH" at -1710.74,6377.42 h60
  text "Round" at -1451.6,6377.42 h60
  text "6" at -2679.31,6253.1 h60
  text "90.55mil (2.300mm)" at -2347.31,6253.1 h60
  text "PTH" at -1710.74,6253.1 h60
  text "Round" at -1451.6,6253.1 h60
  text "2" at -2679.31,6128.78 h60
  text "214.57mil (5.450mm)" at -2347.31,6128.78 h60
  text "PTH" at -1710.74,6128.78 h60
  text "Round" at -1451.6,6128.78 h60
  text "F" at -3005.16,6118.78 h55.25
  text "202 Total" at -2679.31,6004.46 h60
  text ".Layer_Name" at -4149.47,-1063.99 h60

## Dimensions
0,0 to 0,2727 on M2 Board Dimensions
0,0 to 2665,0 on M2 Board Dimensions
-4726.47,-605.5 to -3726.47,-605.5 on M2 Board Dimensions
